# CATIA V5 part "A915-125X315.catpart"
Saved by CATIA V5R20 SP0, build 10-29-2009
Part number: A915-125X315
Source: Unknown
Property "A": "75.000"
Property "ARTICLENO": "A915-125X315"
Property "BOMINFO": "A915-125X315"
Property "CODE": "A915-125X315"
Property "CREATOR": "CADENAS GmbH"
Property "D": "13.500"
Property "D1": "20.000"
Property "FORM": "C"
Property "L": "315.000"
Property "L1": "40.000"
Property "L2": "235.000"
Property "LINA": "A915-125X315"
Property "NB": "A915-125X315"
Property "NBSYN": "$CODE."
Property "NN": "A915"
Property "NT": "VDI 3357 Wear Plates, steel"
Property "SCREW": "M12x25"
Property "SUPPLIER": "CF"
Property "T": "13.000"
Property "W": "125.000"
Bounding box of the stored display mesh (mm): x 0 to 20, y 0 to 315, z -62.5 to 62.5
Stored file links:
  C:\Users\borellobunino\Desktop\3D X SITO CF\A915\GSB_OILLESS_G22501125315\CATIAV5\A915-125X315.catpart
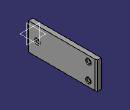
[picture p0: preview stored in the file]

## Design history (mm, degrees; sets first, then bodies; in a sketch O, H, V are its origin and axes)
Body1 "Geometry.1" (main body)
  Solid1 "A915-125X315.catpart": solid without history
